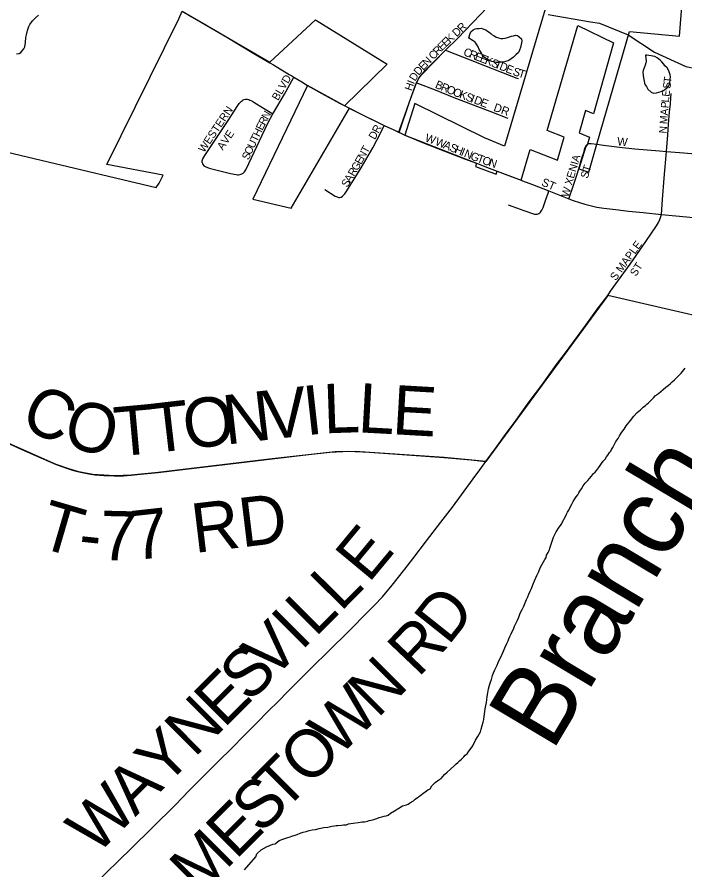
# Model space of a CAD drawing. Extents: x -13.9 to 69.1, y -25.2 to 26.1.
# Drawn here: x 3.245 to 3.981, y 17.053 to 17.993 of the extents above; entities that cross this region are included whole.
import ezdxf

# ---------------------------------------------------------------- set-up
doc = ezdxf.new("R2010")
doc.units = 0
for name, color, linetype in [('GM_X_City_Street', 7, 'Continuous'), ('GM_X_City_Street_Text', 7, 'Continuous'), ('GM_X_Corporation', 7, 'Continuous'), ('GM_X_County_Road', 7, 'Continuous'), ('GM_X_County_Road_Text', 7, 'Continuous'), ('GM_X_Major_River', 7, 'Continuous'), ('GM_X_Minor_Lake', 7, 'Continuous'), ('GM_X_Minor_River', 7, 'Continuous'), ('GM_X_Minor_River_Text', 7, 'Continuous'), ('GM_X_Township_Road', 7, 'Continuous'), ('GM_X_Township_Road_Text', 7, 'Continuous')]:
    doc.layers.add(name, color=color, linetype=linetype)

msp = doc.modelspace()

# ---------------------------------------------------------------- linework, layer by layer
at = {"layer": 'GM_X_City_Street'}
for points in [[(3.71757, 17.95665), (3.7309, 17.96983)], [(3.6855, 17.92078), (3.6864, 17.92261), (3.68776, 17.92497), (3.68924, 17.9272), (3.69096, 17.92927), (3.69555, 17.93455), (3.70724, 17.94644), (3.71757, 17.95665)], [(3.71757, 17.95665), (3.71922, 17.95599), (3.74466, 17.94585), (3.76055, 17.93968), (3.779, 17.93251), (3.79596, 17.92592), (3.79806, 17.92524)], [(3.52366, 17.94279), (3.52777, 17.94037), (3.54514, 17.92997), (3.54803, 17.92823), (3.55034, 17.92685)], [(3.52712, 17.8863), (3.52775, 17.88749), (3.53985, 17.90812), (3.5499, 17.92606), (3.55034, 17.92685)], [(3.55034, 17.92685), (3.55911, 17.92162), (3.56531, 17.91778)], [(3.66594, 17.86614), (3.66671, 17.86834), (3.67468, 17.8913), (3.67771, 17.89958), (3.68238, 17.91301), (3.68475, 17.91922), (3.6855, 17.92078)], [(3.6855, 17.92078), (3.68664, 17.92034), (3.70607, 17.91284), (3.72675, 17.90459), (3.76624, 17.8893), (3.78496, 17.88209), (3.78601, 17.88172)], [(3.44919, 17.83286), (3.44927, 17.83464), (3.45, 17.83686), (3.45201, 17.84038), (3.4777, 17.87908), (3.48852, 17.8956), (3.49013, 17.89764), (3.49138, 17.89923), (3.49249, 17.90041), (3.49345, 17.90119), (3.49441, 17.90183), (3.49541, 17.90227), (3.49702, 17.90266), (3.49922, 17.90257), (3.50044, 17.90224), (3.50184, 17.90164), (3.50379, 17.90065), (3.50627, 17.89922), (3.51691, 17.89258), (3.52594, 17.88702), (3.52712, 17.8863)], [(3.96097, 17.84498), (3.96248, 17.86334), (3.96334, 17.87503), (3.96448, 17.88812), (3.96537, 17.8976), (3.96596, 17.90406), (3.96639, 17.90874)], [(3.44919, 17.83286), (3.44961, 17.83127), (3.45021, 17.83007), (3.45101, 17.82905), (3.45233, 17.82826), (3.45683, 17.82665), (3.48055, 17.82076), (3.48653, 17.81942), (3.48795, 17.81922), (3.48926, 17.81929), (3.49058, 17.81945), (3.49199, 17.81982), (3.49306, 17.82024), (3.49438, 17.82118), (3.49565, 17.82237), (3.49657, 17.82346), (3.49738, 17.82471), (3.50064, 17.8316), (3.51252, 17.85669), (3.52172, 17.87613), (3.52712, 17.8863)], [(3.58449, 17.8031), (3.59591, 17.79576), (3.59793, 17.79482), (3.59954, 17.79438), (3.60063, 17.79433), (3.60224, 17.79473), (3.60372, 17.79552), (3.60502, 17.79662), (3.60653, 17.79835), (3.60883, 17.8017), (3.62428, 17.82702), (3.63732, 17.84908), (3.6418, 17.85726), (3.64753, 17.86878), (3.64994, 17.87363)], [(3.66048, 17.86862), (3.66594, 17.86614)], [(3.66594, 17.86614), (3.67277, 17.86303), (3.68261, 17.85874), (3.69024, 17.85555), (3.70882, 17.84817), (3.72697, 17.84129), (3.73838, 17.83695), (3.75167, 17.83189), (3.76544, 17.82663), (3.77429, 17.82324), (3.78493, 17.81917), (3.80069, 17.81324), (3.80236, 17.81262)], [(3.88421, 17.85293), (3.89163, 17.8518), (3.90934, 17.84985), (3.92624, 17.848), (3.95321, 17.84564), (3.96097, 17.84498)], [(3.95538, 17.77564), (3.9566, 17.79197), (3.95854, 17.81553), (3.96097, 17.84498)], [(3.96097, 17.84498), (3.98006, 17.84336), (3.99255, 17.84228), (4.00966, 17.84081), (4.04898, 17.83743), (4.08147, 17.83411), (4.1242, 17.82975), (4.14183, 17.82805), (4.16497, 17.82582)], [(3.85342, 17.79286), (3.8541, 17.79484), (3.85744, 17.80452), (3.86209, 17.81869), (3.86435, 17.82594)], [(3.80236, 17.81262), (3.8133, 17.80855), (3.83149, 17.80142)], [(3.78643, 17.78607), (3.79169, 17.7842), (3.8037, 17.77992), (3.81443, 17.77609), (3.81559, 17.77578), (3.8168, 17.77565), (3.81767, 17.77566), (3.81865, 17.77579), (3.81955, 17.77609), (3.82038, 17.77654), (3.82138, 17.77727), (3.82229, 17.7782), (3.82306, 17.77916), (3.82373, 17.78028), (3.82445, 17.78175), (3.82499, 17.78311), (3.82773, 17.79084), (3.83057, 17.79883), (3.83149, 17.80142)], [(3.83149, 17.80142), (3.85161, 17.79353), (3.85342, 17.79286)], [(3.85342, 17.79286), (3.85835, 17.791), (3.86513, 17.78851), (3.87091, 17.78669), (3.87679, 17.78525), (3.88434, 17.78365), (3.89195, 17.78238), (3.90512, 17.78084), (3.91936, 17.77923), (3.93529, 17.77766), (3.95538, 17.77564)], [(3.89951, 17.69099), (3.91103, 17.70727), (3.92087, 17.72085), (3.93495, 17.7408), (3.93815, 17.74567), (3.95006, 17.76289), (3.95221, 17.76665), (3.95368, 17.77012), (3.95538, 17.77564)], [(3.95538, 17.77564), (3.97146, 17.77403), (3.99066, 17.77209), (4.02531, 17.76854), (4.05827, 17.76524), (4.09169, 17.76208), (4.12413, 17.75877), (4.15879, 17.75552)], [(3.89621, 17.68632), (3.89951, 17.69099)]]:
    msp.add_lwpolyline(points, dxfattribs=at)
at = {"layer": 'GM_X_Corporation'}
for points in [[(3.23311, 17.8445), (3.27165, 17.83539), (3.39845, 17.8054), (3.40166, 17.81001), (3.4062, 17.81879), (3.3439, 17.83057), (3.42356, 17.99117), (3.42708, 17.99959), (3.52374, 17.94329), (3.57419, 17.99014), (3.65305, 17.94111), (3.60617, 17.89539), (3.56531, 17.91778), (3.50509, 17.79249), (3.54737, 17.78242), (3.61168, 17.8925), (3.6236, 17.88643), (3.64994, 17.87363), (3.66048, 17.86862), (3.66619, 17.86602), (3.67771, 17.89958), (3.68551, 17.92078), (3.6885, 17.92608), (3.69096, 17.92927), (3.71757, 17.95665), (3.7309, 17.96983), (3.79643, 18.03839)], [(3.83424, 18.02587), (3.78251, 17.85069), (3.76055, 17.8598), (3.6837, 17.89788), (3.67277, 17.86303), (3.75167, 17.83189), (3.75041, 17.82846), (3.77332, 17.82006), (3.77429, 17.82323), (3.80069, 17.81324), (3.81077, 17.84725), (3.84077, 17.83522), (3.84814, 17.8607), (3.82937, 17.86811), (3.86324, 17.98383), (3.90266, 17.9648), (3.88074, 17.88661), (3.87163, 17.89003), (3.8648, 17.86544), (3.87613, 17.86054), (3.87395, 17.85308), (3.87205, 17.85045), (3.86435, 17.82594), (3.87537, 17.82226), (3.88421, 17.85293), (3.92029, 17.97716), (3.97555, 17.97192), (3.98024, 18.03285)], [(4.0776, 17.64436), (3.89621, 17.68632), (3.77411, 17.51969), (3.76176, 17.5031), (3.71588, 17.50753), (3.6177, 17.5143), (3.59572, 17.51374), (3.52627, 17.506), (3.4005, 17.49113), (3.37082, 17.48803), (3.35289, 17.48727), (3.32874, 17.48891), (3.31885, 17.49055), (3.31311, 17.49185), (3.30209, 17.49493), (3.2881, 17.49986), (3.23275, 17.52438)]]:
    msp.add_lwpolyline(points, dxfattribs=at)
at = {"layer": 'GM_X_County_Road'}
for points in [[(3.42708, 17.9996), (3.43707, 17.99387), (3.44868, 17.98701), (3.47435, 17.97188), (3.50628, 17.95306), (3.52366, 17.94279)], [(3.56531, 17.91778), (3.58124, 17.90869), (3.58859, 17.90472), (3.60067, 17.89829), (3.61168, 17.8925)], [(3.61168, 17.8925), (3.6118, 17.89244), (3.6236, 17.88643), (3.64551, 17.87575), (3.64994, 17.87363)], [(3.64994, 17.87363), (3.66048, 17.86862)], [(3.76176, 17.5031), (3.77446, 17.52017), (3.7826, 17.53144), (3.7953, 17.54867), (3.80977, 17.56892), (3.8236, 17.58746), (3.83996, 17.60997), (3.84955, 17.62303), (3.86716, 17.64662), (3.87226, 17.6536), (3.8851, 17.67139), (3.89621, 17.68632)], [(3.75523, 17.49402), (3.76176, 17.5031)], [(3.32883, 17.03596), (3.37112, 17.07699), (3.39402, 17.09941), (3.41959, 17.12486), (3.43485, 17.14039), (3.45856, 17.16441), (3.46751, 17.17326), (3.48138, 17.18691), (3.49598, 17.20146), (3.50725, 17.21286), (3.52458, 17.23035), (3.53061, 17.23648), (3.54635, 17.25231), (3.57148, 17.27738), (3.58736, 17.29305), (3.61217, 17.31764), (3.63076, 17.3363), (3.63923, 17.34486), (3.64788, 17.3541), (3.65133, 17.35797), (3.65724, 17.36508), (3.67273, 17.38451), (3.68152, 17.39599), (3.69652, 17.4158), (3.71235, 17.43644), (3.725, 17.45297), (3.73511, 17.46636), (3.74811, 17.48411), (3.75523, 17.49402)]]:
    msp.add_lwpolyline(points, dxfattribs=at)
at = {"layer": 'GM_X_Major_River'}
for points in [[(3.24451, 17.95267), (3.24756, 17.953), (3.24926, 17.95407), (3.25062, 17.95587), (3.25267, 17.95803), (3.2537, 17.9602), (3.25442, 17.96492), (3.25482, 17.97073), (3.25552, 17.97363), (3.25658, 17.97835), (3.25797, 17.98269), (3.25935, 17.98486), (3.26209, 17.98883), (3.2655, 17.99243), (3.2689, 17.9953)], [(3.83078, 17.9959), (3.87742, 17.98798), (3.88715, 17.98632), (3.91888, 17.97364), (3.94781, 17.95447), (3.98252, 17.93846), (4.03549, 17.92749), (4.11619, 17.90574), (4.18499, 17.91296), (4.21738, 17.91771), (4.2384, 17.92597), (4.25916, 17.93823), (4.26844, 17.9482), (4.28713, 17.9943)]]:
    msp.add_lwpolyline(points, dxfattribs=at)
at = {"layer": 'GM_X_Minor_Lake'}
for points in [[(3.74461, 17.97517), (3.74537, 17.97678), (3.74776, 17.97893), (3.75013, 17.98), (3.75182, 17.98034), (3.75453, 17.98067), (3.75689, 17.98101), (3.75857, 17.98026), (3.76194, 17.97913), (3.76361, 17.97765), (3.76562, 17.97653), (3.7673, 17.97506), (3.76897, 17.97359), (3.77065, 17.97284), (3.77333, 17.97099), (3.77569, 17.97023), (3.77838, 17.96947), (3.78074, 17.96944), (3.78311, 17.96978), (3.78582, 17.97047), (3.78785, 17.97117), (3.79022, 17.97187), (3.79225, 17.97257), (3.79462, 17.97327), (3.79698, 17.97288), (3.79865, 17.97141), (3.80133, 17.96919), (3.80164, 17.96664), (3.80022, 17.95939), (3.79884, 17.95649), (3.79781, 17.95396), (3.79508, 17.95145), (3.79236, 17.94894), (3.78997, 17.94715), (3.78828, 17.94607), (3.78658, 17.94501), (3.78353, 17.94395), (3.78082, 17.94326), (3.77812, 17.94329), (3.77609, 17.94295), (3.77339, 17.94298), (3.77036, 17.94375), (3.76834, 17.94413), (3.76599, 17.94525), (3.76364, 17.94637), (3.76163, 17.94785), (3.75995, 17.94896), (3.75795, 17.95153), (3.75663, 17.95409), (3.75463, 17.95739), (3.75331, 17.96032), (3.75165, 17.96325), (3.74999, 17.96545), (3.74798, 17.96693), (3.74596, 17.96804), (3.74395, 17.96952), (3.74328, 17.96989), (3.74328, 17.97026)], [(3.74328, 17.97026), (3.74461, 17.97517)], [(3.93786, 17.95117), (3.93881, 17.94461), (3.93811, 17.9428), (3.93741, 17.9399), (3.93637, 17.93701), (3.93533, 17.93411), (3.93497, 17.9323), (3.93527, 17.92866), (3.93559, 17.92611), (3.93591, 17.92428), (3.93656, 17.92246), (3.93688, 17.92027), (3.93754, 17.91844), (3.93887, 17.91661), (3.94053, 17.91368), (3.94421, 17.91036), (3.9469, 17.90924), (3.94994, 17.90957), (3.95265, 17.91026), (3.95535, 17.91095), (3.95773, 17.91202), (3.95943, 17.91345), (3.96147, 17.91488), (3.96352, 17.9174), (3.9649, 17.9203), (3.96528, 17.92465), (3.9653, 17.9272), (3.96499, 17.92939), (3.96433, 17.93158), (3.96368, 17.93377), (3.96168, 17.93706), (3.95934, 17.93927), (3.95801, 17.94111), (3.95601, 17.94368), (3.95434, 17.94515), (3.95267, 17.94663), (3.95066, 17.94811), (3.94831, 17.94959), (3.94595, 17.94998), (3.94426, 17.95037), (3.94157, 17.95076), (3.93921, 17.95116), (3.93786, 17.95117)]]:
    msp.add_lwpolyline(points, dxfattribs=at)
at = {"layer": 'GM_X_Minor_River'}
for points in [[(3.94901, 17.57609), (3.95207, 17.57823), (3.9548, 17.58038), (3.95752, 17.58253), (3.96024, 17.58504), (3.96296, 17.58683), (3.96534, 17.58898), (3.96739, 17.59114), (3.96977, 17.59329), (3.97182, 17.59508), (3.97386, 17.59724), (3.97556, 17.59867), (3.97727, 17.60047), (3.97864, 17.60228), (3.98001, 17.60408), (3.98171, 17.60624)], [(3.767, 17.26009), (3.76804, 17.26298), (3.7691, 17.26733), (3.77048, 17.27022), (3.77186, 17.27348), (3.77289, 17.27565), (3.77427, 17.27854), (3.77531, 17.28144), (3.77669, 17.28433), (3.77841, 17.28759), (3.78151, 17.29409), (3.7829, 17.29771), (3.78497, 17.30242), (3.78635, 17.30531), (3.78739, 17.30784), (3.78842, 17.31037), (3.7898, 17.31327), (3.79084, 17.3158), (3.79222, 17.31833), (3.7936, 17.32158), (3.79498, 17.32448), (3.7967, 17.32809), (3.79842, 17.33171), (3.79982, 17.33606), (3.80188, 17.34003), (3.80361, 17.34365), (3.80533, 17.34726), (3.80671, 17.35088), (3.8081, 17.35414), (3.80948, 17.35703), (3.81086, 17.36029), (3.81224, 17.36318), (3.81363, 17.36716), (3.81569, 17.3715), (3.81812, 17.37766), (3.82018, 17.38199), (3.82191, 17.38597), (3.82363, 17.38923), (3.82535, 17.39248), (3.82706, 17.395), (3.82844, 17.39753), (3.8288, 17.40007), (3.83052, 17.40296), (3.83155, 17.40513), (3.83294, 17.40875), (3.83433, 17.4131), (3.83642, 17.41962), (3.83952, 17.42576), (3.84261, 17.43082), (3.84534, 17.43406), (3.84638, 17.43659), (3.84981, 17.44273), (3.85085, 17.44526), (3.85188, 17.44743), (3.85325, 17.4496), (3.85532, 17.45358), (3.85669, 17.4561), (3.85807, 17.459), (3.86013, 17.46188), (3.8615, 17.46441), (3.86321, 17.46657), (3.86458, 17.46874), (3.86561, 17.47054), (3.86733, 17.47307), (3.86938, 17.47632), (3.87144, 17.4792), (3.87416, 17.48208), (3.87622, 17.4846), (3.87827, 17.48712), (3.88066, 17.49), (3.88236, 17.49143), (3.88373, 17.49323), (3.88612, 17.49611), (3.88783, 17.49864), (3.88954, 17.5008), (3.89126, 17.50369), (3.8933, 17.50585), (3.89502, 17.50837), (3.89638, 17.51017), (3.8981, 17.51306), (3.8998, 17.5145), (3.90049, 17.51631), (3.90187, 17.51847), (3.90325, 17.52173), (3.90531, 17.52534), (3.9077, 17.52858), (3.90942, 17.53147), (3.91114, 17.53436), (3.91285, 17.53688), (3.91455, 17.53868), (3.91662, 17.54266), (3.9214, 17.54842), (3.92516, 17.5531), (3.92891, 17.55706), (3.93232, 17.56029), (3.93539, 17.56316), (3.93777, 17.56495), (3.93947, 17.56638), (3.94117, 17.56782), (3.94662, 17.57321), (3.94901, 17.57609)], [(3.4959, 17.05293), (3.50823, 17.06721), (3.50928, 17.07083), (3.51438, 17.07513), (3.52016, 17.07834), (3.52456, 17.0801), (3.52693, 17.08116), (3.52964, 17.08186), (3.53406, 17.08544), (3.53914, 17.0872), (3.54355, 17.0886), (3.54625, 17.08929), (3.54795, 17.09), (3.55167, 17.09141), (3.55404, 17.09211), (3.5571, 17.09353), (3.56048, 17.09458), (3.56386, 17.09526), (3.56725, 17.09631), (3.5703, 17.097), (3.57402, 17.09769), (3.57807, 17.09873), (3.58315, 17.09976), (3.58754, 17.10007), (3.59194, 17.1011), (3.59498, 17.10143), (3.59701, 17.10177), (3.59869, 17.10175), (3.60275, 17.10243), (3.60512, 17.10276), (3.60816, 17.10273), (3.61053, 17.10379), (3.6156, 17.10445), (3.62101, 17.10512), (3.6254, 17.10579), (3.6281, 17.10612), (3.6298, 17.10646), (3.63149, 17.10681), (3.63318, 17.10751), (3.63555, 17.10785), (3.63825, 17.10854), (3.64164, 17.10959), (3.64435, 17.11065), (3.64706, 17.11135), (3.64977, 17.11204), (3.65214, 17.11274), (3.65417, 17.11344), (3.65689, 17.11559), (3.6613, 17.11808), (3.66606, 17.12093), (3.67013, 17.12343), (3.67453, 17.12483), (3.67623, 17.12554), (3.67792, 17.12661), (3.67996, 17.12804), (3.682, 17.12911), (3.68404, 17.1309), (3.68642, 17.13269), (3.6888, 17.13411), (3.6905, 17.13555), (3.69255, 17.13734), (3.69493, 17.13913), (3.69798, 17.14128), (3.70036, 17.14234), (3.70242, 17.14559), (3.70616, 17.14918), (3.71025, 17.1524), (3.71262, 17.15383), (3.71467, 17.15598), (3.71638, 17.15815), (3.71944, 17.16065), (3.72694, 17.16784), (3.72898, 17.16963), (3.73102, 17.17142), (3.73273, 17.17322), (3.73511, 17.17501), (3.7375, 17.17753), (3.7392, 17.17932), (3.74124, 17.18075), (3.7433, 17.184), (3.74569, 17.18725), (3.74774, 17.18977), (3.75051, 17.19592), (3.75291, 17.19989), (3.75462, 17.20278), (3.756, 17.20531), (3.7567, 17.20821), (3.75775, 17.21219), (3.7588, 17.21582), (3.75951, 17.21872), (3.75988, 17.22199), (3.76094, 17.22743), (3.76131, 17.2307), (3.76202, 17.23433), (3.76273, 17.23759), (3.7631, 17.24049), (3.76347, 17.24413), (3.76418, 17.24812), (3.7649, 17.25247), (3.76595, 17.25646), (3.767, 17.26009)]]:
    msp.add_lwpolyline(points, dxfattribs=at)
at = {"layer": 'GM_X_Township_Road'}
for points in [[(3.86435, 17.82594), (3.86775, 17.83763), (3.87016, 17.84503), (3.87072, 17.84704), (3.87146, 17.84931), (3.87263, 17.8516), (3.87395, 17.85307)], [(3.87395, 17.85307), (3.87479, 17.8535), (3.87545, 17.8537), (3.87691, 17.85383), (3.87812, 17.8537), (3.88421, 17.85293)], [(3.23275, 17.52438), (3.25025, 17.51636), (3.27117, 17.50704), (3.2881, 17.49986), (3.30169, 17.49505), (3.3061, 17.49369), (3.31017, 17.49252), (3.31517, 17.49133), (3.32039, 17.49023), (3.32621, 17.48929), (3.33128, 17.48854), (3.33616, 17.48803), (3.34058, 17.48766), (3.35213, 17.48725), (3.36258, 17.4875), (3.37082, 17.48803), (3.37742, 17.4887), (3.4005, 17.49113), (3.42796, 17.49437), (3.48947, 17.50179), (3.52627, 17.50599), (3.56636, 17.51079), (3.59002, 17.51339), (3.60439, 17.51427), (3.61046, 17.51447), (3.61769, 17.5143), (3.63374, 17.51363), (3.71588, 17.50753), (3.74563, 17.50486), (3.76176, 17.5031)]]:
    msp.add_lwpolyline(points, dxfattribs=at)

# ---------------------------------------------------------------- texts
at = {"layer": 'GM_X_City_Street_Text'}
for s, height, rotation, p in [('R', 0.00879, 43.0523, (3.73526, 17.97597)), ('D', 0.00879, 43.05449, (3.72966, 17.97074)), ('E', 0.00879, 43.33635, (3.71793, 17.95974)), ('K', 0.00879, 43.04802, (3.72238, 17.96394)), ('R', 0.00876, 46.32826, (3.70888, 17.95048)), ('E', 0.00877, 44.92995, (3.71362, 17.95545)), ('C', 0.00899, 338.28864, (3.73638, 17.95135)), ('N', 0.00876, 46.30724, (3.69718, 17.93823)), ('C', 0.00876, 46.30545, (3.7041, 17.94548)), ('R', 0.00899, 338.29449, (3.74264, 17.94886)), ('E', 0.00899, 338.28752, (3.7489, 17.94637)), ('E', 0.00899, 338.28752, (3.75446, 17.94416)), ('K', 0.00899, 338.29659, (3.76002, 17.94194)), ('E', 0.00876, 46.36138, (3.69294, 17.93378)), ('S', 0.00899, 338.28752, (3.76698, 17.93917)), ('I', 0.00899, 338.28152, (3.77254, 17.93696)), ('D', 0.00899, 338.31164, (3.77602, 17.93557)), ('E', 0.00899, 338.30948, (3.78297, 17.9328)), ('D', 0.00862, 58.35153, (3.68399, 17.92179)), ('D', 0.00874, 48.09471, (3.68783, 17.92809)), ('S', 0.009, 339.28583, (3.79076, 17.9297)), ('T', 0.00902, 343.05525, (3.7969, 17.9274)), ('BLVD', 0.008607, 59.84807, (3.53284, 17.90041)), ('H', 0.0085, 70.97292, (3.68018, 17.91113)), ('I', 0.00853, 68.29722, (3.68272, 17.9185)), ('B', 0.00898, 336.74799, (3.70528, 17.91545)), ('R', 0.00898, 336.72425, (3.71148, 17.91278)), ('S', 0.00844, 82.68149, (3.96525, 17.91365)), ('T', 0.00844, 82.68866, (3.96606, 17.91997)), ('O', 0.00898, 336.74971, (3.71768, 17.91012)), ('O', 0.00899, 338.31164, (3.72478, 17.90707)), ('K', 0.009, 339.44795, (3.7319, 17.90424)), ('E', 0.00843, 83.2215, (3.9642, 17.90497)), ('S', 0.009, 339.48745, (3.7389, 17.90161)), ('I', 0.009, 339.50798, (3.74451, 17.89952)), ('D', 0.009, 339.48746, (3.74801, 17.89821)), ('E', 0.009, 339.4839, (3.75501, 17.89559)), ('L', 0.00843, 85.01373, (3.96365, 17.8987)), ('WESTERN', 0.008647, 56.12722, (3.45135, 17.84307)), ('DR', 0.009001, 340.26649, (3.76969, 17.88995)), ('A', 0.00843, 85.72808, (3.96259, 17.88442)), ('P', 0.00843, 85.72727, (3.96318, 17.89237)), ('R', 0.00858, 62.92098, (3.51831, 17.87318)), ('N', 0.0086, 60.4696, (3.52147, 17.87938)), ('M', 0.00843, 85.72863, (3.96187, 17.87488)), ('E', 0.00856, 64.63073, (3.51564, 17.86756)), ('R', 0.00859, 61.93539, (3.64343, 17.8643)), ('AVE', 0.008654, 55.51288, (3.47191, 17.84578)), ('T', 0.00856, 64.63073, (3.50958, 17.85477)), ('H', 0.00856, 64.6557, (3.51228, 17.86046)), ('D', 0.00859, 61.14197, (3.63959, 17.85732)), ('W', 0.009, 340.28193, (3.69407, 17.85645)), ('N', 0.00843, 85.72808, (3.9611, 17.86455)), ('U', 0.00856, 64.63538, (3.50621, 17.84766)), ('W', 0.00898, 337.73487, (3.70526, 17.85244)), ('A', 0.00898, 337.71793, (3.71426, 17.84876)), ('W', 0.00906, 355.27163, (3.90646, 17.85175)), ('O', 0.00856, 64.6557, (3.50285, 17.84056)), ('N', 0.00859, 61.17057, (3.62742, 17.83533)), ('T', 0.00859, 61.15556, (3.6312, 17.84219)), ('S', 0.00898, 337.73645, (3.72119, 17.84591)), ('H', 0.00898, 337.71996, (3.72674, 17.84365)), ('I', 0.00898, 337.75452, (3.73367, 17.84081)), ('N', 0.00898, 337.7415, (3.73714, 17.83939)), ('S', 0.00856, 64.63073, (3.50015, 17.83487)), ('E', 0.0086, 60.92722, (3.62435, 17.82982)), ('G', 0.00899, 338.08616, (3.74411, 17.83653)), ('T', 0.009, 340.4966, (3.75141, 17.83361)), ('O', 0.00901, 341.50108, (3.75718, 17.83156)), ('N', 0.00901, 341.5241, (3.76427, 17.8292)), ('W XENIA', 0.008482, 73.90536, (3.85293, 17.79393)), ('R', 0.00862, 58.692, (3.61653, 17.81674)), ('G', 0.00861, 59.43279, (3.62025, 17.82286)), ('ST', 0.00849, 72.79441, (3.87411, 17.81455)), ('A', 0.00862, 58.67478, (3.61246, 17.81006)), ('S', 0.00862, 58.67904, (3.60922, 17.80472)), ('ST', 0.008977, 336.7121, (3.82242, 17.80777)), ('S MAPLE', 0.008671, 53.97045, (3.90504, 17.70188)), ('ST', 0.008635, 57.23337, (3.92733, 17.70655))]:
    msp.add_text(s, height=height, rotation=rotation, dxfattribs=at).set_placement(p)
at = {"layer": 'GM_X_County_Road_Text'}
for s, height, rotation, p in [('E', 0.05227, 50.3311, (3.63274, 17.36834)), ('L', 0.05261, 45.25676, (3.60174, 17.33673)), ('D', 0.05219, 51.51485, (3.7204, 17.29932)), ('L', 0.05263, 44.9237, (3.57378, 17.30884)), ('I', 0.05263, 44.92438, (3.55855, 17.29366)), ('V', 0.05263, 44.91661, (3.52592, 17.26113)), ('R', 0.05253, 46.44648, (3.68735, 17.26423)), ('S', 0.05263, 44.91286, (3.5009, 17.23618)), ('N', 0.05263, 44.95653, (3.64232, 17.2192)), ('E', 0.05263, 44.92139, (3.47318, 17.20853)), ('W', 0.05263, 44.91754, (3.59934, 17.17634)), ('N', 0.05263, 44.91675, (3.44055, 17.176)), ('Y', 0.05263, 44.91675, (3.40793, 17.14347)), ('O', 0.05263, 44.9091, (3.5667, 17.14381)), ('T', 0.05263, 44.91278, (3.53897, 17.11616)), ('A', 0.05263, 44.91675, (3.3753, 17.11094)), ('W', 0.05263, 44.91792, (3.33235, 17.06811)), ('S', 0.05263, 44.91256, (3.51396, 17.09122)), ('E', 0.05263, 44.91278, (3.48622, 17.06357)), ('M', 0.05263, 44.91297, (3.44598, 17.02345))]:
    msp.add_text(s, height=height, rotation=rotation, dxfattribs=at).set_placement(p)
at = {"layer": 'GM_X_Minor_River_Text'}
msp.add_text('Branch', height=0.086138, rotation=59.14304, dxfattribs=at).set_placement((3.83482, 17.18212))
at = {"layer": 'GM_X_Township_Road_Text'}
for s, height, rotation, p in [('C', 0.05377, 334.63328, (3.24638, 17.54267)), ('V', 0.05434, 6.60108, (3.51952, 17.5268)), ('I', 0.05434, 6.33194, (3.56369, 17.53191)), ('L', 0.05438, 1.93677, (3.58339, 17.53414)), ('L', 0.05437, 356.87285, (3.62008, 17.53543)), ('E', 0.05437, 356.69746, (3.6578, 17.53337)), ('O', 0.05434, 6.62562, (3.43108, 17.51653)), ('N', 0.05434, 6.62053, (3.4753, 17.52167)), ('O', 0.05418, 345.49514, (3.29373, 17.52125)), ('T', 0.05436, 5.16802, (3.35451, 17.50863)), ('T', 0.05434, 6.62326, (3.39348, 17.51217)), ('T', 0.05413, 343.69277, (3.26613, 17.40957)), ('RD', 0.054337, 6.87548, (3.44081, 17.40221)), ('7', 0.05434, 6.33729, (3.37422, 17.39429)), ('7', 0.05438, 358.67923, (3.33635, 17.39471)), ('-', 0.05435, 354.05299, (3.31162, 17.39712))]:
    msp.add_text(s, height=height, rotation=rotation, dxfattribs=at).set_placement(p)

doc.saveas('drawing.dxf')
